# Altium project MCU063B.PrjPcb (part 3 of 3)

## Sheet MCU063B_Emulator.SchDoc
size 431 x 279 mm; Date: Not shown in title block; ApprovedBy: Not shown in title block; CheckedBy: Not shown in title block; Author: Not shown in title block; CompanyName: Not shown in title block; DrawnBy: Cody Watkins; Engineer: Not shown in title block; Organization: Not shown in title block; Address1: Not shown in title block; Address2: Not shown in title block; Address3: Not shown in title block; Address4: Not shown in title block; DocumentNumber: 9; Revision: Use project parameter SCH_Rev; SheetNumber: 9; SheetTotal: 11; PageSetup: Record=PageOptions¦CenterHorizontal=True¦CenterVertical=True¦PrintScale=1.00¦XCorrection=1.00¦YCorrection=1.00¦PrintKind=0¦BorderSize=5000000¦LeftOffset=0¦BottomOffset=0¦Orientation=2¦PaperLength=1000¦PaperWidth=1000¦Scale=100¦PaperSource=15¦PrintQuality=600¦MediaType=1¦DitherType=10¦PaperKind=Letter¦PrintScaleMode=1
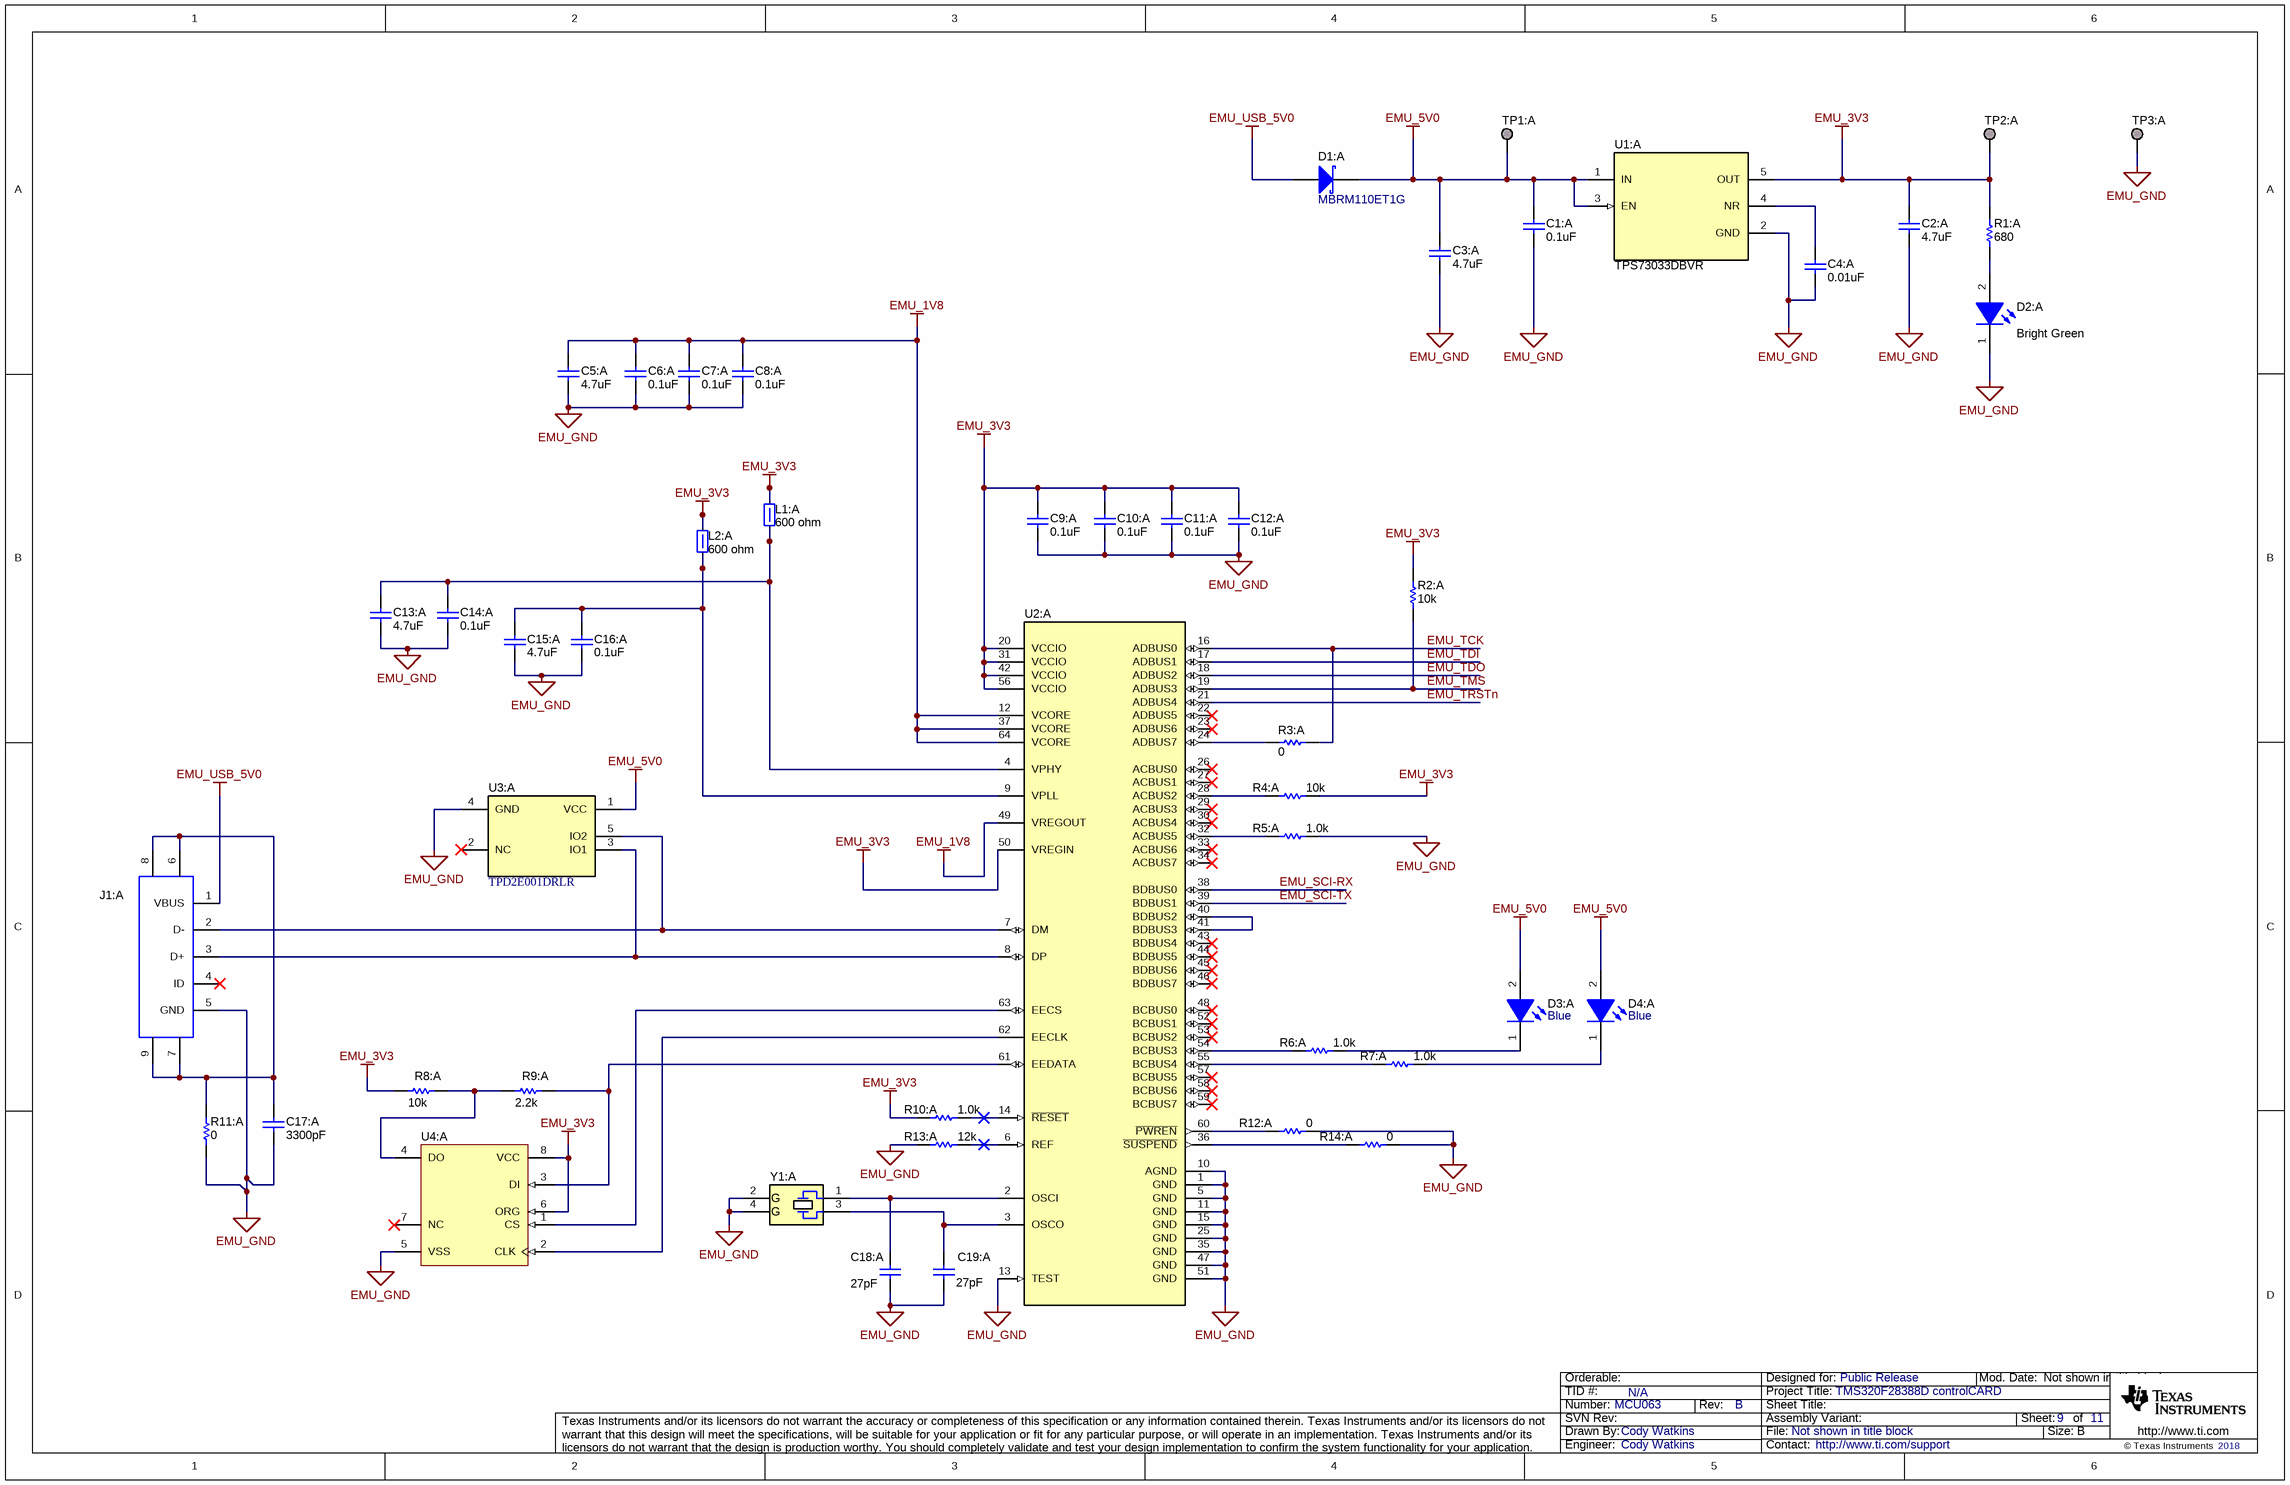
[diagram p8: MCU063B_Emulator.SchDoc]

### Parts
C1:A  ValueDisplayed: 0.1uF  [0402]  (hidden comment: CL05B104KP5NNNC)
C2:A  ValueDisplayed: 4.7uF  [0603]  (hidden comment: C0603C475K9PACTU)
C3:A  ValueDisplayed: 4.7uF  [0603]  (hidden comment: C0603C475K9PACTU)
C4:A  ValueDisplayed: 0.01uF  [0402]  (hidden comment: 0402ZC103KAT2A)
C5:A  ValueDisplayed: 4.7uF  [0603]  (hidden comment: C0603C475K9PACTU)
C6:A  ValueDisplayed: 0.1uF  [0402]  (hidden comment: CL05B104KP5NNNC)
C7:A  ValueDisplayed: 0.1uF  [0402]  (hidden comment: CL05B104KP5NNNC)
C8:A  ValueDisplayed: 0.1uF  [0402]  (hidden comment: CL05B104KP5NNNC)
C9:A  ValueDisplayed: 0.1uF  [0402]  (hidden comment: CL05B104KP5NNNC)
C10:A  ValueDisplayed: 0.1uF  [0402]  (hidden comment: CL05B104KP5NNNC)
C11:A  ValueDisplayed: 0.1uF  [0402]  (hidden comment: CL05B104KP5NNNC)
C12:A  ValueDisplayed: 0.1uF  [0402]  (hidden comment: CL05B104KP5NNNC)
C13:A  ValueDisplayed: 4.7uF  [0603]  (hidden comment: C0603C475K9PACTU)
C14:A  ValueDisplayed: 0.1uF  [0402]  (hidden comment: CL05B104KP5NNNC)
C15:A  ValueDisplayed: 4.7uF  [0603]  (hidden comment: C0603C475K9PACTU)
C16:A  ValueDisplayed: 0.1uF  [0402]  (hidden comment: CL05B104KP5NNNC)
C17:A  ValueDisplayed: 3300pF  [0402]  (hidden comment: CGA2B2X7R1H332K050BA)
C18:A  ValueDisplayed: 27pF  [0402]  (hidden comment: C0402C270J5GACTU)
C19:A  ValueDisplayed: 27pF  [0402]  (hidden comment: C0402C270J5GACTU)
D1:A  MBRM110ET1G  [POWERMITE]
D2:A  value Bright Green  [WL-SMCW_Green_0805]  (hidden comment: 150080VS75000)
D3:A  value Blue  [WL-SMCW_Blue_0805]  (hidden comment: 150080BS75000)
D4:A  value Blue  [WL-SMCW_Blue_0805]  (hidden comment: 150080BS75000)
J1:A  65100516121  [Wurth_65100516121]  (value not drawn)
L1:A  value 600 ohm  [0805_HV]  (hidden comment: HZ0805E601R-10)
L2:A  value 600 ohm  [0805_HV]  (hidden comment: HZ0805E601R-10)
R1:A  ValueDisplayed: 680  [0402]  (hidden comment: CRCW0402680RJNED)
R2:A  ValueDisplayed: 10k  [0402]  (hidden comment: CRCW040210K0JNED)
R3:A  ValueDisplayed: 0  [0402]  (hidden comment: CRCW04020000Z0ED)
R4:A  ValueDisplayed: 10k  [0402]  (hidden comment: CRCW040210K0JNED)
R5:A  ValueDisplayed: 1.0k  [0402]  (hidden comment: CRCW04021K00JNED)
R6:A  ValueDisplayed: 1.0k  [0402]  (hidden comment: CRCW04021K00JNED)
R7:A  ValueDisplayed: 1.0k  [0402]  (hidden comment: CRCW04021K00JNED)
R8:A  ValueDisplayed: 10k  [0402]  (hidden comment: CRCW040210K0JNED)
R9:A  ValueDisplayed: 2.2k  [0402]  (hidden comment: CRCW04022K20JNED)
R10:A  ValueDisplayed: 1.0k  [0402]  (hidden comment: CRCW04021K00JNED)
R11:A  ValueDisplayed: 0  [0402]  (hidden comment: CRCW04020000Z0ED)
R12:A  ValueDisplayed: 0  [0402]  (hidden comment: CRCW04020000Z0ED)
R13:A  ValueDisplayed: 12k  [0402]  (hidden comment: CRCW040212K0JNED)
R14:A  ValueDisplayed: 0  [0402]  (hidden comment: CRCW04020000Z0ED)
TP1:A  TESTPOINT  [TP_50MIL-25MILHOLE]  (value not drawn)  (no BOM)
TP2:A  TESTPOINT  [TP_50MIL-25MILHOLE]  (value not drawn)  (no BOM)
TP3:A  TESTPOINT  [TP_50MIL-25MILHOLE]  (value not drawn)  (no BOM)
U1:A  TPS73033DBVR  [DBV0005A_N]
U2:A  FT2232HL-REEL  [LQFP64_N]  (value not drawn)
U3:A  TPD2E001DRLR  [DRL0005A]
U4:A  93LC56C-I/SN  [SOIC-8]  (value not drawn)
Y1:A  ECS-120-20-30B-TR  [ECS_ECX-53B]  (value not drawn)

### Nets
EMU_1V8: C5:A.2 C6:A.2 C7:A.2 C8:A.2 U2:A.12(VCORE) U2:A.37(VCORE) U2:A.49(VREGOUT) U2:A.64(VCORE)
EMU_3V3: C2:A.1 C9:A.2 C10:A.2 C11:A.2 C12:A.2 L1:A.2 L2:A.2 R1:A.1 R2:A.2 R4:A.2 R8:A.1 R10:A.1 TP2:A.1 U1:A.5(OUT) U2:A.20(VCCIO) U2:A.31(VCCIO) U2:A.42(VCCIO) U2:A.50(VREGIN) U2:A.56(VCCIO) U4:A.6(ORG) U4:A.8(VCC)
EMU_5V0: C1:A.2 C3:A.1 D1:A.1(K) D3:A.2(A) D4:A.2(A) TP1:A.1 U1:A.1(IN) U1:A.3(EN) U3:A.1(VCC)
EMU_GND: C1:A.1 C2:A.2 C3:A.2 C4:A.1 C5:A.1 C6:A.1 C7:A.1 C8:A.1 C9:A.1 C10:A.1 C11:A.1 C12:A.1 C13:A.2 C14:A.1 C15:A.2 C16:A.1 C17:A.1 C18:A.1 C19:A.1 D2:A.1(K) J1:A.5(GND) R5:A.2 R11:A.2 R12:A.1 R13:A.1 R14:A.1 TP3:A.1 U1:A.2(GND) U2:A.1(GND) U2:A.5(GND) U2:A.10(AGND) U2:A.11(GND) U2:A.13(TEST) U2:A.15(GND) U2:A.25(GND) U2:A.35(GND) U2:A.47(GND) U2:A.51(GND) U3:A.4(GND) U4:A.5(VSS) Y1:A.2(GND) Y1:A.4(GND)
EMU_USB_5V0: D1:A.2(A) J1:A.1(VBUS)
EMU_SCI-RX: U2:A.38(BDBUS0)
EMU_SCI-TX: U2:A.39(BDBUS1)
EMU_TCK: R3:A.1 U2:A.16(ADBUS0)
EMU_TDI: U2:A.17(ADBUS1)
EMU_TDO: U2:A.18(ADBUS2)
EMU_TMS: R2:A.1 U2:A.19(ADBUS3)
EMU_TRSTn: U2:A.21(ADBUS4)
NetC4:A_2: C4:A.2 U1:A.4(NR)
NetC13:A_1: C13:A.1 C14:A.2 L1:A.1 U2:A.4(VPHY)
NetC15:A_1: C15:A.1 C16:A.2 L2:A.1 U2:A.9(VPLL)
NetC17:A_2: C17:A.2 J1:A.6 J1:A.7 J1:A.8 J1:A.9 R11:A.1
NetC18:A_2: C18:A.2 U2:A.2(OSCI) Y1:A.1
NetC19:A_2: C19:A.2 U2:A.3(OSCO) Y1:A.3
NetD2:A_2: D2:A.2(A) R1:A.2
NetD3:A_1: D3:A.1(K) R6:A.2
NetD4:A_1: D4:A.1(K) R7:A.2
NetJ1:A_2: J1:A.2(D-) U2:A.7(DM) U3:A.5(IO2)
NetJ1:A_3: J1:A.3(D+) U2:A.8(DP) U3:A.3(IO1)
NetR3:A_2: R3:A.2 U2:A.24(ADBUS7)
NetR4:A_1: R4:A.1 U2:A.28(ACBUS2)
NetR5:A_1: R5:A.1 U2:A.32(ACBUS5)
NetR6:A_1: R6:A.1 U2:A.54(BCBUS3)
NetR7:A_1: R7:A.1 U2:A.55(BCBUS4)
NetR8:A_2: R8:A.2 R9:A.1 U4:A.4(DO)
NetR9:A_2: R9:A.2 U2:A.61(EEDATA) U4:A.3(DI)
NetR10:A_2: R10:A.2 U2:A.14(~{RESET})
NetR12:A_2: R12:A.2 U2:A.60(~{PWREN})
NetR13:A_2: R13:A.2 U2:A.6(REF)
NetR14:A_2: R14:A.2 U2:A.36(~{SUSPEND})
NetU2:A_40: U2:A.40(BDBUS2) U2:A.41(BDBUS3)
NetU2:A_62: U2:A.62(EECLK) U4:A.2(CLK)
NetU2:A_63: U2:A.63(EECS) U4:A.1(CS)

Not connected (* = marked no-connect by the designer): J1:A 4(ID)*; U2:A 22(ADBUS5)* 23(ADBUS6)* 26(ACBUS0)* 27(ACBUS1)* 29(ACBUS3)* 30(ACBUS4)* 33(ACBUS6)* 34(ACBUS7)* 43(BDBUS4)* 44(BDBUS5)* 45(BDBUS6)* 46(BDBUS7)* 48(BCBUS0)* 52(BCBUS1)* 53(BCBUS2)* 57(BCBUS5)* 58(BCBUS6)* 59(BCBUS7)*; U3:A 2(NC)*; U4:A 7(NC)*

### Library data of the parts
C1:A C6:A C7:A C8:A C9:A C10:A C11:A C12:A C14:A C16:A = CMP-0006343-2: CAP, CERM, 0.1 uF, 10 V, +/- 10%, X7R, 0402; Manufacturer: Samsung Electro-Mechanics; Polarized: N; Value: 0.1uF; U/M: EA; Cap_F: 100nF; Value1: Unknown; VDC_V: 10V; TaMin_C: -55°C; TaMax_C: 125°C; AEC Category: Q200; SizeArea_mm2: 0.5; SizeAreaWB_mm2: 3; SizeX_mm: 1; SizeZ_mm: 0.6
C2:A C3:A C5:A C13:A C15:A = CMP-0006950-5: CAP, CERM, 4.7 uF, 6.3 V, +/- 10%, X5R, 0603; Manufacturer: Kemet; TaMin_C: -55°C; ESR_ohm: 6m; Polarized: N; SizeAreaWB_mm2: 4.68; Value1: 0.006 ohm; U/M: EA; Value: 4.7uF; TaMax_C: 85°C; SizeZ_mm: 1; SizeX_mm: 1.6; SizeY_mm: 0.8; Value2: 6.3V; SizeArea_mm2: 1.28; Cap_F: 4.7µF; IRMS_A: 7.24A; AEC Category: Q200
C4:A = CMP-0006203-2: CAP, CERM, 0.01 uF, 10 V, +/- 10%, X7R, 0402; Manufacturer: AVX; Polarized: N; Value: 0.01uF; U/M: EA; Cap_F: 10nF; Value1: Unknown; Value2: 10V; TaMin_C: -55°C; TaMax_C: 125°C; AEC Category: Q200; SizeArea_mm2: 0.5; SizeAreaWB_mm2: 3; SizeX_mm: 1; SizeZ_mm: 0.6
C17:A = CMP-0006319-2: CAP, CERM, 3300 pF, 50 V, +/- 10%, X7R, AEC-Q200 Grade 1, 0402; Manufacturer: TDK; TaMin_C: -55°C; ESR_ohm: 7.85178d; Polarized: N; SizeAreaWB_mm2: 3; Value1: 0.785178 ohm; U/M: EA; Value: 3300pF; TaMax_C: 125°C; SizeZ_mm: 0.6; SizeX_mm: 1; SizeY_mm: 0.5; Value2: 50V; AEC Qualified: Y; Cap_F: 3.3nF; IRMS_A: 2.72902dA; AEC Category: Q200
C18:A C19:A = CMP-0750098-1: CAP, CERM, 27 pF, 50 V,+/- 5%, C0G/NP0, 0402; Manufacturer: Kemet; SizeX_mm: 1; TaMin_C: -55°C; Value: 27pF; Polarized: N; SizeAreaWB_mm2: 3; SizeArea_mm2: 0.5; Green_REACh: Passed; Green_Lifecycle: Active; Value2: 50V; U/M: EA; AEC Category: Q200; SizeZ_mm: 0.6; TaMax_C: 125°C
D1:A = CMP-0028747-2: Diode, Schottky, 10 V, 1 A, AEC-Q101, POWERMITE; Manufacturer: ON Semiconductor; Vf_V: 530mV; Value: 10V; Value1: 1A; Value2: 0.53V; TJmax_C: 150°C; AEC Category: Q101; AEC Qualified: Y; SizeAreaWB_mm2: 14.945; SizeArea_mm2: 7.995; SizeX_mm: 3.9; SizeY_mm: 2.05; SizeZ_mm: 1.15; Green_Lifecycle: Not Set; Green_REACh: Incomplete
D2:A = CMP-0002960-2: LED, Bright Green, SMD; Manufacturer: Wurth Elektronik; Type: AlInGaP; Vf_V: 2V; Io_A: 20mA; Vr_V: 5V; Tjmax_C: 85°C; Power_TotalModule: 72mW; Value1: 0.072W; Angle: 140; U/M: EA
D3:A D4:A = CMP-0002959-3: LED, Blue, SMD; Manufacturer: Wurth Elektronik; Vf_V: 3.2V; Value1: 0.105W; Angle: 140; Type: InGaN; Power_TotalModule: 105mW; Tjmax_C: 85°C; Vr_V: 5V; Io_A: 20mA
J1:A = CMP-0054809-1: Connector, Receptacle, USB Mini B 2.0, SMT; Manufacturer: Wurth Elektronik; Pitch_mm: 0.8; Gender: Female; Row_Count: 1; ContactFinish: Gold; Current_A: 1A; Voltage_V: 30V; Cert_UL: Y; CNHeader: FALSE; CT: TRUE; Green_Lifecycle: Active; Green_REACh: Passed
L1:A L2:A = CMP-0003398-1: Ferrite Bead, 600 ohm @ 100 MHz, 0.5 A, 0805; Manufacturer: Laird-Signal Integrity Products; Imax_A: 5dA; DCR_ohm: 3d; Value1: 0.3 ohm; Value2: 0.5A; ZTyp@100MHz_Ohm: 600; SizeArea_mm2: 2.5; SizeAreaWB_mm2: 6.75; SizeX_mm: 2; SizeY_mm: 1.25; SizeZ_mm: 1.45
R1:A = CMP-0026962-3: RES, 680, 5%, 0.063 W, AEC-Q200 Grade 0, 0402; Manufacturer: Vishay-Dale; Value: 680; Value_Code: 680R; Power_W: 63mW; Value2: 0.063W; VDC_V: 50V; TempCo: 200 ppm/C; EIA_Code: E24; AEC Category: Q200; AEC Qualified: Y; AEC Grade: 0; SizeArea_mm2: 0.5; SizeX_mm: 1; SizeZ_mm: 0.6
R2:A R4:A R8:A = CMP-0026825-5: RES, 10 k, 5%, 0.063 W, AEC-Q200 Grade 0, 0402; Manufacturer: Vishay-Dale; Value: 10k; Value_Code: 10k0; Power_W: 63mW; Value2: 0.063W; VDC_V: 50V; TempCo: 200 ppm/C; EIA_Code: E24; AEC Category: Q200; AEC Qualified: Y; AEC Grade: 0; SizeArea_mm2: 0.5; SizeX_mm: 1; SizeZ_mm: 0.6
R3:A R11:A R12:A R14:A = CMP-0026822-3: RES, 0, 5%, 0.063 W, AEC-Q200 Grade 0, 0402; Manufacturer: Vishay-Dale; Value: 0; Value_Code: 0000; Power_W: 63mW; Value2: 0.063W; VDC_V: 50V; TempCo: 200 ppm/C; EIA_Code: E24; AEC Category: Q200; AEC Qualified: Y; SizeArea_mm2: 0.5; SizeX_mm: 1; SizeZ_mm: 0.6
R5:A R6:A R7:A R10:A = CMP-0026852-3: RES, 1.0 k, 5%, 0.063 W, AEC-Q200 Grade 0, 0402; Manufacturer: Vishay-Dale; Value: 1.0k; Res_ohm: 1k; Value_Code: 1k00; Power_W: 63mW; Value2: 0.063W; VDC_V: 50V; TempCo: 200 ppm/C; EIA_Code: E24; AEC Category: Q200; AEC Qualified: Y; AEC Grade: 0; SizeArea_mm2: 0.5; SizeX_mm: 1; SizeZ_mm: 0.6
R9:A = CMP-0026890-5: RES, 2.2 k, 5%, 0.063 W, AEC-Q200 Grade 0, 0402; Manufacturer: Vishay-Dale; Value: 2.2k; Value_Code: 2k20; Power_W: 63mW; Value2: 0.063W; VDC_V: 50V; TempCo: 200 ppm/C; EIA_Code: E24; AEC Category: Q200; AEC Qualified: Y; AEC Grade: 0; SizeArea_mm2: 0.5; SizeX_mm: 1; SizeZ_mm: 0.6
R13:A = CMP-0026834-3: RES, 12 k, 5%, 0.063 W, AEC-Q200 Grade 0, 0402; Manufacturer: Vishay-Dale; Value: 12k; Value_Code: 12k0; Power_W: 63mW; Value2: 0.063W; VDC_V: 50V; TempCo: 200 ppm/C; EIA_Code: E24; AEC Category: Q200; AEC Qualified: Y; AEC Grade: 0; SizeArea_mm2: 0.5; SizeX_mm: 1; SizeZ_mm: 0.6
TP1:A TP2:A TP3:A = CMP-0078143-3: TEST POINT.  No entry in BOM.
U1:A = CMP-0073823-1: Low-Noise, High PSRR, RF 200-mA Low-Dropout Linear Regulators, DBV0005A (SOT-23-5); Alternate PartNumber: TPS73033DBVT; Manufacturer: Texas Instruments; CompType: IC; U/M: EA; SizeArea_mm2: 8.12; SizeAreaWB_mm2: 14.82; SizeX_mm: 2.8; SizeY_mm: 2.9; SizeZ_mm: 1.45; Green_Lifecycle: Active; Green_REACh: Passed
U2:A = CMP-0004796-1: Dual High Speed USB To Multipurpose UART/FIFO IC, LQFP-64; Manufacturer: FTDI
U3:A = CMP-0043096-2: Low-Capacitance + / - 15 kV ESD-Protection Array for High-Speed Data Interfaces, 2 Channels, -40 to +85 degC, 5-pin SOT (DRL), Green (RoHS & no Sb/Br); Manufacturer: Texas Instruments; Breakdown Voltage(Min)(V): 11; IEC 61000-4-2 Air-Gap(+/- kV): 15; IEC 61000-4-2 Contact(+/- kV): 8; IO Capacitance(Typ)(pF): 1.5; IO Leakage Current(nA): 1; SubFamily: ESD Solution; USB High Speed: TRUE
U4:A = CMP-0005261-2: 2K Microwire Compatible Serial EEPROM, SOIC-8; Manufacturer: Microchip; SizeAreaWB_mm2: 55.131; SizeArea_mm2: 29.351; SizeX_mm: 5.99; SizeY_mm: 4.9; SizeZ_mm: 1.75
Y1:A = CMP-0004646-3: Crystal, 12 MHz, 20pF, SMD; Manufacturer: ECS Inc.; TaMin_C: -20°C; TaMax_C: 70°C; Frequency Stability: +/-50ppm; Frequency_Fixed: 12MHz

## Sheet MCU063B_Emulator_interface.SchDoc
size 431 x 279 mm; Date: Not shown in title block; ApprovedBy: Not shown in title block; CheckedBy: Not shown in title block; Author: Not shown in title block; CompanyName: Not shown in title block; DrawnBy: Cody Watkins; Engineer: Not shown in title block; Organization: Not shown in title block; Address1: Not shown in title block; Address2: Not shown in title block; Address3: Not shown in title block; Address4: Not shown in title block; DocumentNumber: 10; Revision: Use project parameter SCH_Rev; SheetNumber: 10; SheetTotal: 11; PageSetup: Record=PageOptions¦CenterHorizontal=True¦CenterVertical=True¦PrintScale=1.00¦XCorrection=1.00¦YCorrection=1.00¦PrintKind=0¦BorderSize=5000000¦LeftOffset=0¦BottomOffset=0¦Orientation=2¦PaperLength=1000¦PaperWidth=1000¦Scale=100¦PaperSource=15¦PrintQuality=600¦MediaType=1¦DitherType=10¦PaperKind=Letter¦PrintScaleMode=1
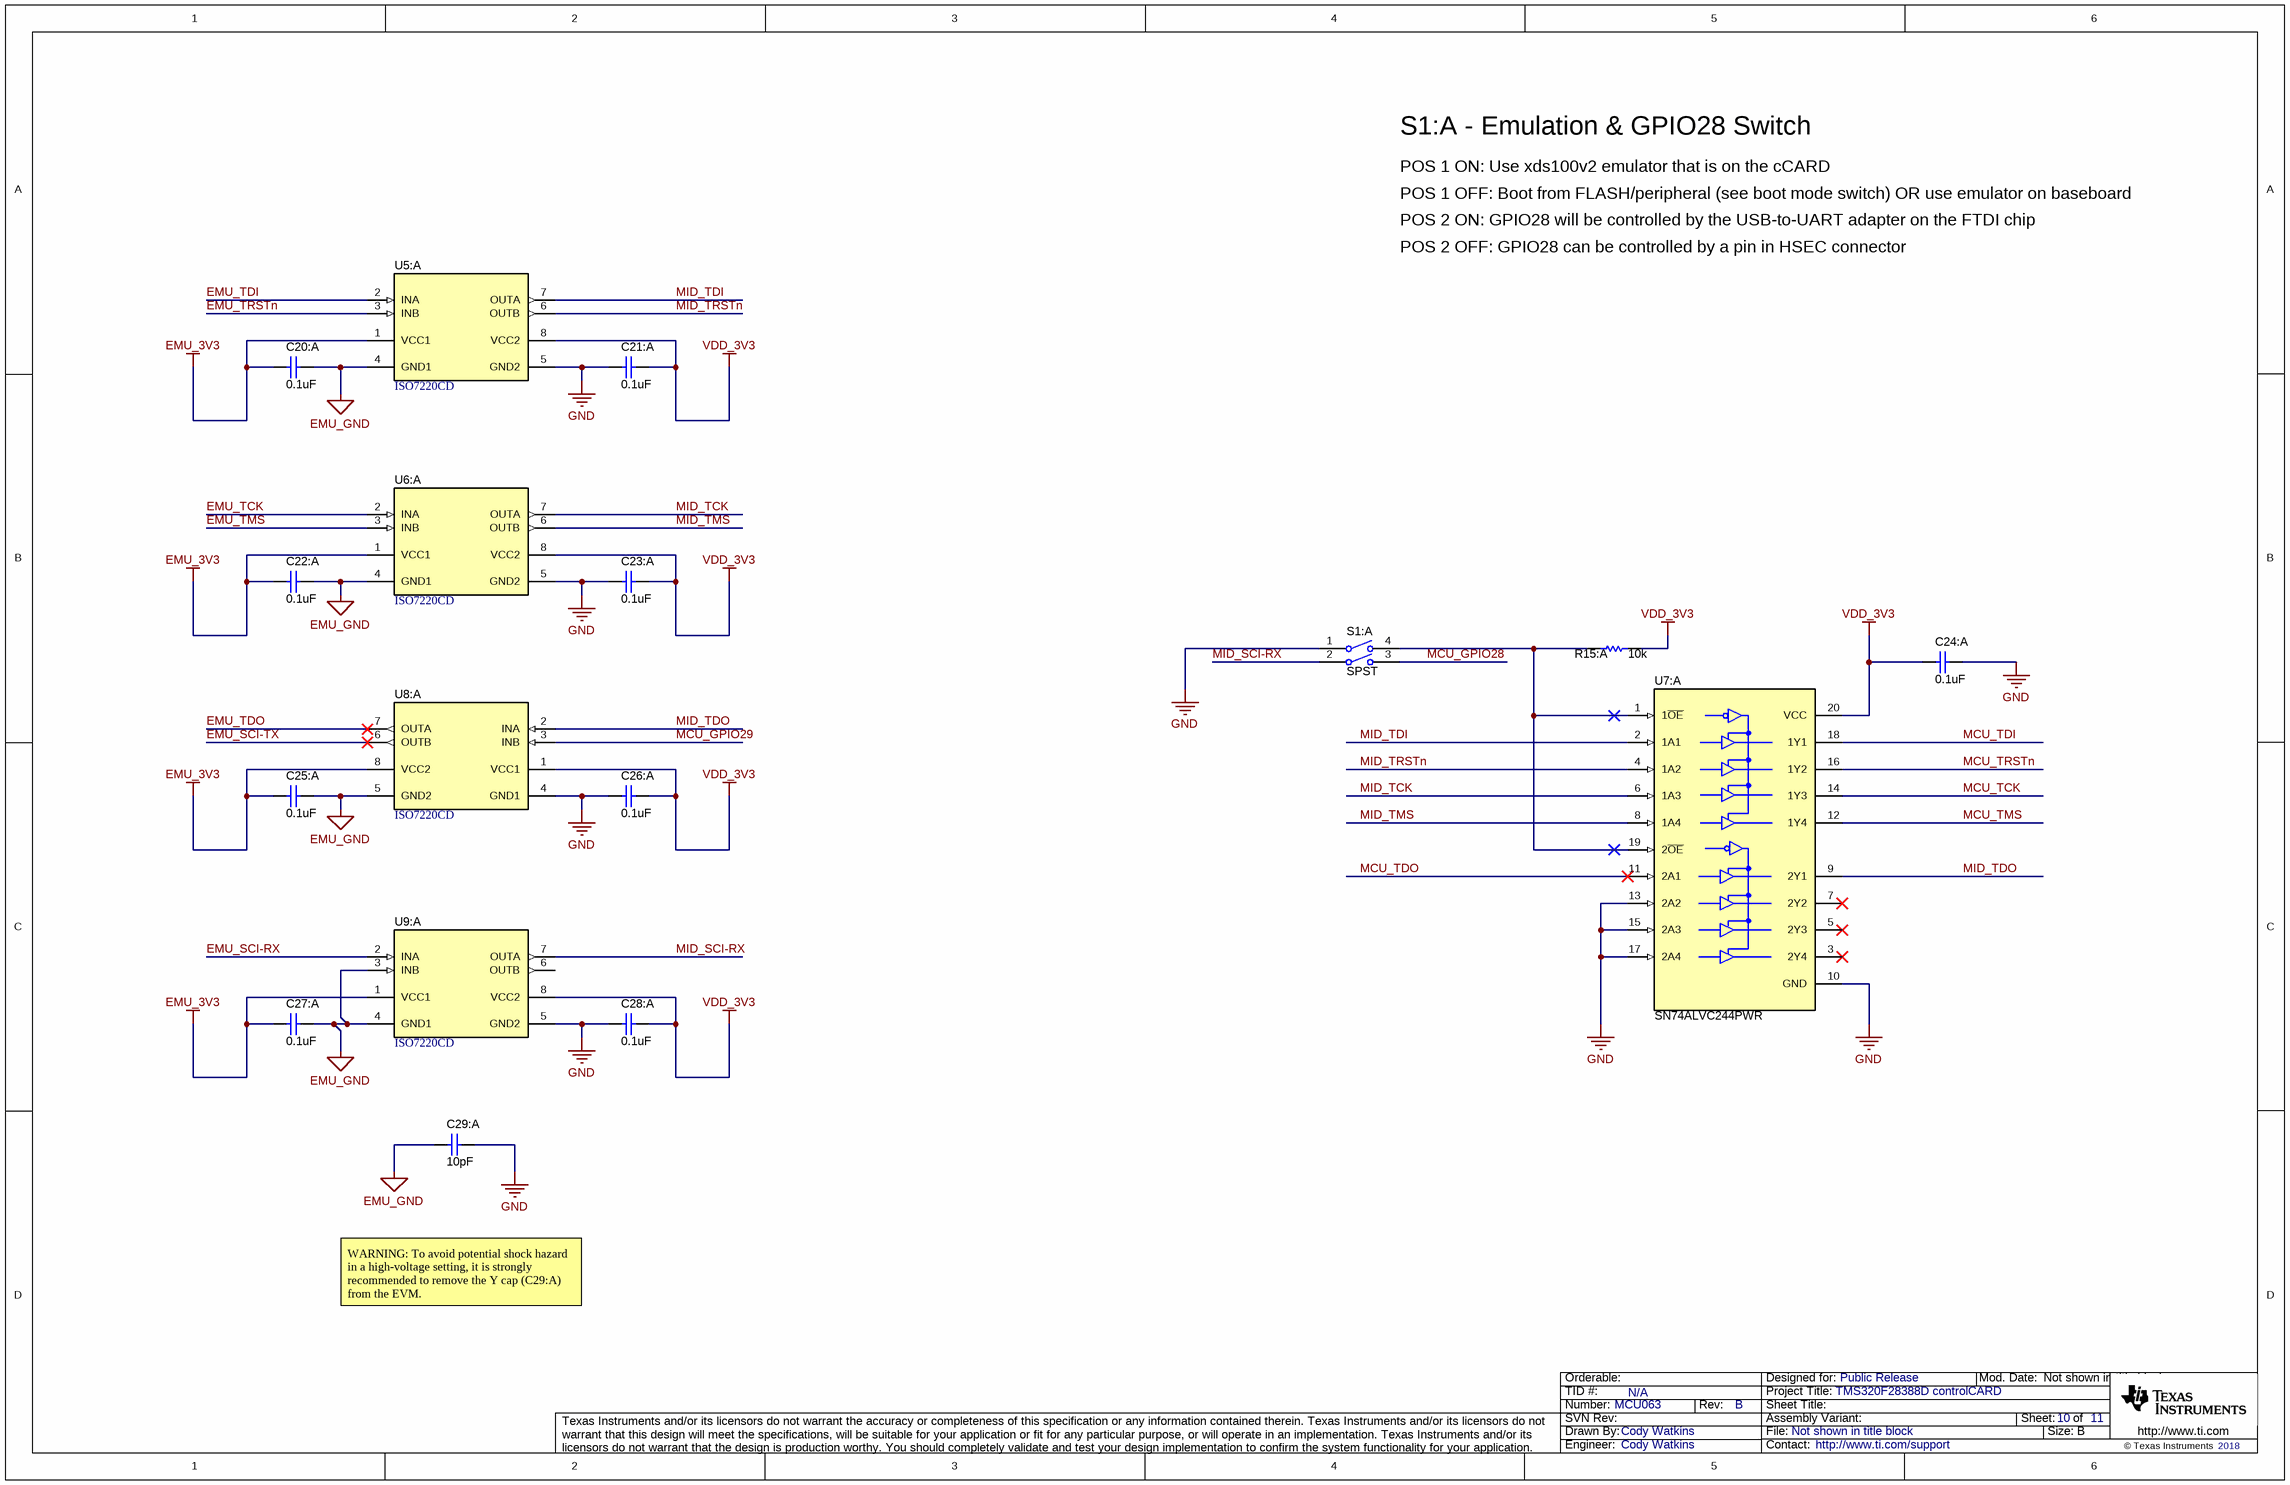
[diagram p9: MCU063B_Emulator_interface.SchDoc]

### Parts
C20:A  ValueDisplayed: 0.1uF  [0402]  (hidden comment: CL05B104KP5NNNC)
C21:A  ValueDisplayed: 0.1uF  [0402]  (hidden comment: CL05B104KP5NNNC)
C22:A  ValueDisplayed: 0.1uF  [0402]  (hidden comment: CL05B104KP5NNNC)
C23:A  ValueDisplayed: 0.1uF  [0402]  (hidden comment: CL05B104KP5NNNC)
C24:A  ValueDisplayed: 0.1uF  [0402]  (hidden comment: CL05B104KP5NNNC)
C25:A  ValueDisplayed: 0.1uF  [0402]  (hidden comment: CL05B104KP5NNNC)
C26:A  ValueDisplayed: 0.1uF  [0402]  (hidden comment: CL05B104KP5NNNC)
C27:A  ValueDisplayed: 0.1uF  [0402]  (hidden comment: CL05B104KP5NNNC)
C28:A  ValueDisplayed: 0.1uF  [0402]  (hidden comment: CL05B104KP5NNNC)
C29:A  ValueDisplayed: 10pF  [1812_180]  (hidden comment: C1812C100JHGACTU)
R15:A  ValueDisplayed: 10k  [0402]  (hidden comment: CRCW040210K0JNED)
S1:A  Circuit: SPST  [SW_218-2LP]  (hidden comment: 218-2LPST)
U5:A  ISO7220CD  [D0008B_N]
U6:A  ISO7220CD  [D0008B_N]
U7:A  SN74ALVC244PWR  [PW0020A_N]
U8:A  ISO7220CD  [D0008B_N]
U9:A  ISO7220CD  [D0008B_N]

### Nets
EMU_3V3: C20:A.2 C22:A.2 C25:A.2 C27:A.2 U5:A.1(VCC1) U6:A.1(VCC1) U8:A.8(VCC2) U9:A.1(VCC1)
EMU_GND: C20:A.1 C22:A.1 C25:A.1 C27:A.1 C29:A.2 U5:A.4(GND1) U6:A.4(GND1) U8:A.5(GND2) U9:A.3(INB) U9:A.4(GND1)
GND: C21:A.2 C23:A.2 C24:A.1 C26:A.2 C28:A.2 C29:A.1 S1:A.1 U5:A.5(GND2) U6:A.5(GND2) U7:A.10(GND) U7:A.13(2A2) U7:A.15(2A3) U7:A.17(2A4) U8:A.4(GND1) U9:A.5(GND2)
VDD_3V3: C21:A.1 C23:A.1 C24:A.2 C26:A.1 C28:A.1 R15:A.2 U5:A.8(VCC2) U6:A.8(VCC2) U7:A.20(VCC) U8:A.1(VCC1) U9:A.8(VCC2)
EMU_SCI-RX: U9:A.2(INA)
EMU_SCI-TX: U8:A.6(OUTB)
EMU_TCK: U6:A.2(INA)
EMU_TDI: U5:A.2(INA)
EMU_TDO: U8:A.7(OUTA)
EMU_TMS: U6:A.3(INB)
EMU_TRSTn: U5:A.3(INB)
MCU_GPIO28: S1:A.3
MCU_GPIO29: U8:A.3(INB)
MCU_TCK: U7:A.14(1Y3)
MCU_TDI: U7:A.18(1Y1)
MCU_TDO: U7:A.11(2A1)
MCU_TMS: U7:A.12(1Y4)
MCU_TRSTn: U7:A.16(1Y2)
MID_SCI-RX: S1:A.2 U9:A.7(OUTA)
MID_TCK: U6:A.7(OUTA) U7:A.6(1A3)
MID_TDI: U5:A.7(OUTA) U7:A.2(1A1)
MID_TDO: U7:A.9(2Y1) U8:A.2(INA)
MID_TMS: U6:A.6(OUTB) U7:A.8(1A4)
MID_TRSTn: U5:A.6(OUTB) U7:A.4(1A2)
NetR15:A_1: R15:A.1 S1:A.4 U7:A.1(1~{OE}) U7:A.19(2~{OE})

Not connected (* = marked no-connect by the designer): U7:A 3(2Y4)* 5(2Y3)* 7(2Y2)*; U9:A 6(OUTB)

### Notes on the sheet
- S1:A - Emulation & GPIO28 Switch
- POS 1 ON: Use xds100v2 emulator that is on the cCARD
- POS 1 OFF: Boot from FLASH/peripheral (see boot mode switch) OR use emulator on baseboard
- POS 2 ON: GPIO28 will be controlled by the USB-to-UART adapter on the FTDI chip
- POS 2 OFF: GPIO28 can be controlled by a pin in HSEC connector
- WARNING: To avoid potential shock hazard in a high-voltage setting, it is strongly recommended to remove the Y cap (C29:A) from the EVM.

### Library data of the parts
C20:A C21:A C22:A C23:A C24:A C25:A C26:A C27:A C28:A = CMP-0006343-2: as C1:A on sheet MCU063B_Emulator
C29:A = CMP-0082066-1: CAP, CERM, 10 pF, 3000 V,+/- 5%, C0G/NP0, AEC-Q200 Grade 1, 1812; Manufacturer: Kemet; SizeAreaWB_mm2: 23.1; SizeArea_mm2: 14.4; AEC Qualified: Y; AEC Category: Q200; Value: 10pF; TaMax_C: 125°C; SizeZ_mm: 1.8; AEC Grade: 1; Polarized: N; TaMin_C: -55°C; SizeY_mm: 3.2; Value2: 3000V; U/M: EA; SizeX_mm: 4.5; Cap_Case: 1812
R15:A = CMP-0026825-5: as R2:A on sheet MCU063B_Emulator
S1:A = CMP-0002230-1: Switch, SPST, 2 Pos, 25mA, 24VDC, SMD; Manufacturer: CTS Electrocomponents; VDC_V: 24V; SwitchFunction: Off-On; PositionCount: 2; CurrentRating_mA: 25A
U5:A U6:A U8:A U9:A = CMP-0029375-1: 25 Mbps Dual Channels, 2 / 0, Digital Isolator, 3.3 V / 5 V, -40 to +125 degC, 8-pin SOIC (D), Green (RoHS & no Sb/Br); Manufacturer: Texas Instruments; Datarate(Mbps): 25; Input Noise Filter: Yes; Insulation Rating(VRMS): 2500; Prop Delay(Max)(ns): 42; Rating: Catalog; Supply Voltage(s)(V): 3.3, 5; TTL/CMOS Input Threshold: TTL
U7:A = CMP-0047070-3: Octal Buffer/Driver With 3-State OUtputs, PW0020A (TSSOP-20); Manufacturer: Texas Instruments; Bits(#): 8; F @ Nom Voltage(Max)(Mhz): 100; ICC @ Nom Voltage(Max)(mA): 0.024; Input Type: LVTTL; Rating: Catalog; tpd @ Nom Voltage(Max)(ns): 4.4,3.1,2.8; VCC(Max)(V): 3.6; VCC(Min)(V): 1.65; Voltage(Nom)(V): 1.8,2.5,2.7,3.3; AEC Category: Q200; AEC Qualified: N; CompType: IC; SizeArea_mm2: 43.56; SizeAreaWB_mm2: 73.96; SizeX_mm: 6.6; SizeZ_mm: 1.2

## Sheet MCU063B_EVM_Hardware.SchDoc
size 431 x 279 mm; Date: Not shown in title block; ApprovedBy: Not shown in title block; CheckedBy: Not shown in title block; Author: Not shown in title block; CompanyName: Not shown in title block; Engineer: Not shown in title block; Organization: Not shown in title block; Address1: Not shown in title block; Address2: Not shown in title block; Address3: Not shown in title block; Address4: Not shown in title block; DocumentNumber: 11; Revision: Use project parameter SCH_Rev; SheetNumber: 11; SheetTotal: 11; PageSetup: Record=PageOptions¦CenterHorizontal=True¦CenterVertical=True¦PrintScale=1.00¦XCorrection=1.00¦YCorrection=1.00¦PrintKind=0¦BorderSize=5000000¦LeftOffset=0¦BottomOffset=0¦Orientation=2¦PaperLength=1000¦PaperWidth=1000¦Scale=100¦PaperSource=15¦PrintQuality=600¦MediaType=1¦DitherType=10¦PaperKind=Letter¦PrintScaleMode=1
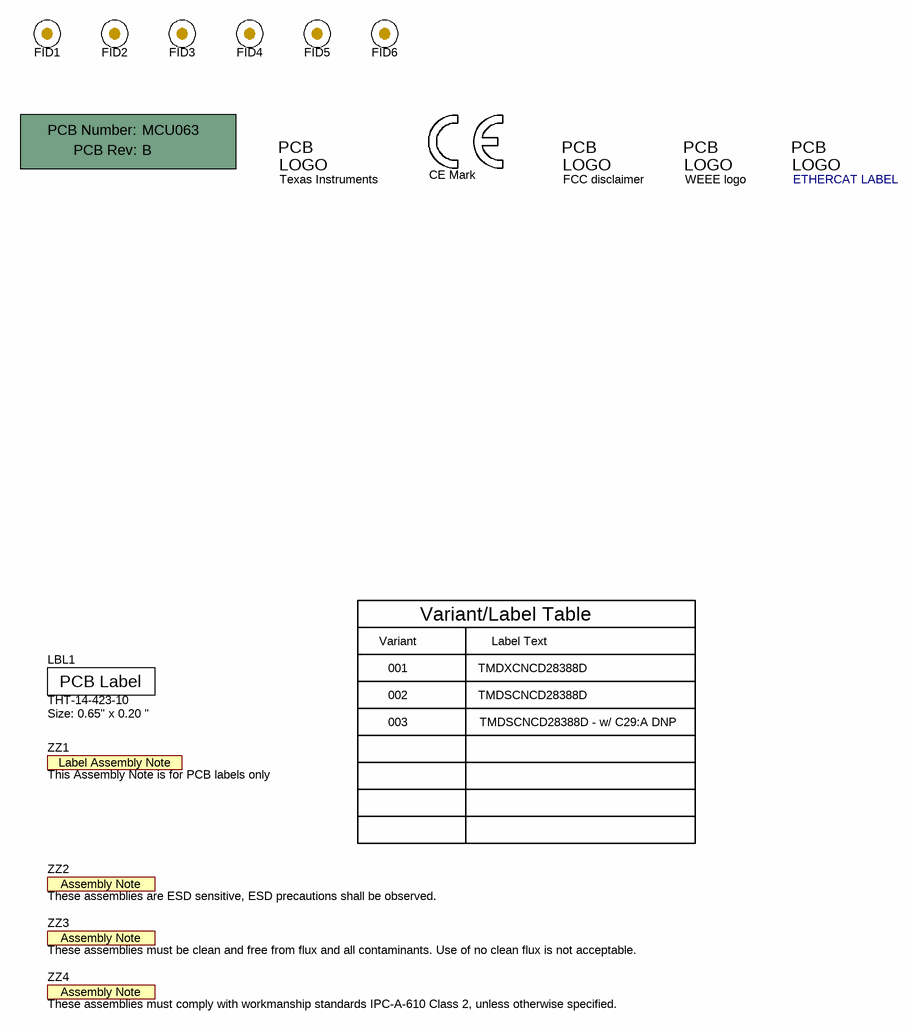
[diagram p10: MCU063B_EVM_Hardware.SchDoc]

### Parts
!PCB1  Printed Circuit Board  (value not drawn)  (mechanical)
FID1  Fiducial  [Fiducial10-20]  (value not drawn)
FID2  Fiducial  [Fiducial10-20]  (value not drawn)
FID3  Fiducial  [Fiducial10-20]  (value not drawn)
FID4  Fiducial  [Fiducial10-20]  (value not drawn)
FID5  Fiducial  [Fiducial10-20]  (value not drawn)
FID6  Fiducial  [Fiducial10-20]  (value not drawn)
LBL1  THT-14-423-10  Note: Size: 0.65" x 0.20 "  [Label_650x200]
Logo1  CE Mark  [CE_Mark_5mm]  (no BOM)
Logo2  Texas Instruments  [TI_Stacked_Overlay_Small]  (no BOM)
Logo3  FCC disclaimer  [FCC_disclaimer]  (no BOM)
Logo4  WEEE logo  [WEEE_Minimum]  (no BOM)
Logo5  ETHERCAT LABEL  [EtherCAT_label]  (no BOM)
ZZ1  This Assembly Note is for PCB labels only  [AssemblyNoteLabel]  (no BOM)
ZZ2  These assemblies are ESD sensitive, ESD precautions shall be observed.  [AssemblyNote]  (no BOM)
ZZ3  These assemblies must be clean and free from flux and all contaminants. Use of no clean flux is not acceptable.  [AssemblyNote]  (no BOM)
ZZ4  These assemblies must comply with workmanship standards IPC-A-610 Class 2, unless otherwise specified.  [AssemblyNote]  (no BOM)

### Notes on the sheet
- Variant
- Variant/Label Table
- Label Text
- 001
- 002
- TMDXCNCD28388D
- TMDSCNCD28388D
- 003
- TMDSCNCD28388D - w/ C29:A DNP

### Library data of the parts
!PCB1 = CMP-0003618-2: Manufacturer: Any; PartNumber: MCU063
FID1-FID6 = CMP-0077181-1: Fiducial mark.  There is nothing to buy or mount.
LBL1 = CMP-0003625-1: Thermal Transfer Printable Labels, 0.650" W x 0.200" H - 10,000 per roll; Manufacturer: Brady
Logo1 = CMP-0074844-1: SymbolCreator: a0412235
Logo2 = CMP-0074838-1: Texas Instrument Corporate Signature; SymbolCreator: a0412235; Lib Reference: TI_Logo; Library Reference: Logo
Logo3 = CMP-0074847-1: FCC_disclaimer
Logo4 = CMP-0074769-1
Logo5 = CMP-0084011-3: EtherCAT logo
ZZ1 = CMP-0003616-3
ZZ2 = CMP-0077236-1
ZZ3 = CMP-0077237-1
ZZ4 = CMP-0077238-1

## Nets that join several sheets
3V3: MCU063B_GPIO (EC1.119), MCU063B_Support (J2.10), MCU063B_Power (10 pins)
EMU_3V3: MCU063B_Emulator (21 pins), MCU063B_Emulator_interface (8 pins)
EMU_GND: MCU063B_Emulator (42 pins), MCU063B_Emulator_interface (10 pins)
GND: MCU063B_GPIO (15 pins), MCU063B_Support (31 pins), MCU063B_ADC (49 pins), MCU063B_Power (120 pins), MCU063B_USB (11 pins), MCU063B_EtherNET (19 pins), MCU063B_EtherCAT (59 pins), MCU063B_Emulator_interface (15 pins)
HSEC_5V0: MCU063B_GPIO (6 pins), MCU063B_Power (D3.2 TP7.1)
USB_5V0: MCU063B_Power (R82.2), MCU063B_USB (5 pins)
VDD_1V2: MCU063B_GPIO (EC1.118), MCU063B_Support (U4.3), MCU063B_Power (25 pins)
VDD_3V3: MCU063B_GPIO (R1.2 R2.1), MCU063B_Support (26 pins), MCU063B_Power (51 pins), MCU063B_USB (R104.1), MCU063B_EtherNET (30 pins), MCU063B_EtherCAT (73 pins), MCU063B_Emulator_interface (11 pins)
VDDA_3V3: MCU063B_ADC (18 pins), MCU063B_Power (6 pins)
ADC_A0A1_N: MCU063B_GPIO (EC1.11), MCU063B_ADC (R52.2)
ADC_A0A1_P: MCU063B_GPIO (EC1.9), MCU063B_ADC (R51.2)
ADC_A2A3_N: MCU063B_GPIO (EC1.17), MCU063B_ADC (R54.2)
ADC_A2A3_P: MCU063B_GPIO (EC1.15), MCU063B_ADC (R53.2)
ADC_A4A5_N: MCU063B_GPIO (EC1.23), MCU063B_ADC (R56.2)
ADC_A4A5_P: MCU063B_GPIO (EC1.21), MCU063B_ADC (R55.2)
ADC_B0B1_N: MCU063B_GPIO (EC1.14), MCU063B_ADC (R61.2)
ADC_B0B1_P: MCU063B_GPIO (EC1.12), MCU063B_ADC (R60.2)
ADC_B2B3_N: MCU063B_GPIO (EC1.20), MCU063B_ADC (R63.2)
ADC_B2B3_P: MCU063B_GPIO (EC1.18), MCU063B_ADC (R62.2)
ADC_B4B5_N: MCU063B_GPIO (EC1.26), MCU063B_ADC (R65.2)
ADC_B4B5_P: MCU063B_GPIO (EC1.24), MCU063B_ADC (R64.2)
ADC_C2C3_N: MCU063B_GPIO (EC1.33), MCU063B_ADC (R68.2)
ADC_C2C3_P: MCU063B_GPIO (EC1.31), MCU063B_ADC (R67.2)
ADC_C4C5_N: MCU063B_GPIO (EC1.39), MCU063B_ADC (R70.2)
ADC_C4C5_P: MCU063B_GPIO (EC1.37), MCU063B_ADC (R69.2)
ADC_D0D1_N: MCU063B_GPIO (EC1.30), MCU063B_ADC (R73.2)
ADC_D0D1_P: MCU063B_GPIO (EC1.28), MCU063B_ADC (R72.2)
ADC_D2D3_N: MCU063B_GPIO (EC1.36), MCU063B_ADC (R75.2)
ADC_D2D3_P: MCU063B_GPIO (EC1.34), MCU063B_ADC (R74.2)
ADC_D4D5_N: MCU063B_GPIO (EC1.42), MCU063B_ADC (R81.2)
ADC_D4D5_P: MCU063B_GPIO (EC1.40), MCU063B_ADC (R76.2)
ADC_IN1415_N: MCU063B_GPIO (EC1.27), MCU063B_ADC (R59.2)
ADC_IN1415_P: MCU063B_GPIO (EC1.25), MCU063B_ADC (R58.2)
EMU_SCI-RX: MCU063B_Emulator (U2:A.38), MCU063B_Emulator_interface (U9:A.2)
EMU_SCI-TX: MCU063B_Emulator (U2:A.39), MCU063B_Emulator_interface (U8:A.6)
EMU_TCK: MCU063B_Emulator (R3:A.1 U2:A.16), MCU063B_Emulator_interface (U6:A.2)
EMU_TDI: MCU063B_Emulator (U2:A.17), MCU063B_Emulator_interface (U5:A.2)
EMU_TDO: MCU063B_Emulator (U2:A.18), MCU063B_Emulator_interface (U8:A.7)
EMU_TMS: MCU063B_Emulator (R2:A.1 U2:A.19), MCU063B_Emulator_interface (U6:A.3)
EMU_TRSTn: MCU063B_Emulator (U2:A.21), MCU063B_Emulator_interface (U5:A.3)
ENET_PHY_CLK: MCU063B_Support (R35.2), MCU063B_EtherNET (U17.23)
ERRORSTS: MCU063B_GPIO (EC2.178), MCU063B_Support (R18.2 TP1.1 U1.U19)
HSEC_ADC-VREFHI: MCU063B_GPIO (EC1.45), MCU063B_ADC (R47.1)
HSEC_GPIO8: MCU063B_GPIO (EC1.57), MCU063B_Support (R21.2)
HSEC_GPIO9: MCU063B_GPIO (EC1.59), MCU063B_Support (R23.2)
HSEC_GPIO10: MCU063B_GPIO (EC1.61), MCU063B_Support (R22.1)
HSEC_GPIO25: MCU063B_GPIO (EC1.77), MCU063B_Support (R24.1)
HSEC_GPIO26: MCU063B_GPIO (EC1.79), MCU063B_Support (R25.2)
HSEC_GPIO27: MCU063B_GPIO (EC1.81), MCU063B_Support (R27.2)
MCU_GPIO8: MCU063B_GPIO (U1.G2), MCU063B_Support (J2.1 R21.1)
MCU_GPIO9: MCU063B_GPIO (U1.G3), MCU063B_Support (J2.3 R23.1)
MCU_GPIO10: MCU063B_GPIO (U1.B2), MCU063B_Support (J2.2 R22.2)
MCU_GPIO25: MCU063B_GPIO (U1.K2), MCU063B_Support (J2.6 R24.2)
MCU_GPIO26: MCU063B_GPIO (U1.K1), MCU063B_Support (J2.5 R25.1)
MCU_GPIO27: MCU063B_GPIO (U1.L1), MCU063B_Support (J2.7 R27.1)
MCU_GPIO28: MCU063B_GPIO (EC1.76 U1.V11), MCU063B_Emulator_interface (S1:A.3)
MCU_GPIO29: MCU063B_GPIO (EC1.78 U1.W11), MCU063B_Emulator_interface (U8:A.3)
MCU_GPIO31: MCU063B_GPIO (EC1.82 U1.U11), MCU063B_Support (R11.1 U2.1)
MCU_GPIO34: MCU063B_GPIO (EC1.86 U1.U14), MCU063B_Support (R12.1 U2.3)
MCU_GPIO42: MCU063B_GPIO (U1.D19), MCU063B_USB (R95.1)
MCU_GPIO43: MCU063B_GPIO (U1.C19), MCU063B_USB (R96.1)
MCU_GPIO44: MCU063B_GPIO (U1.K18), MCU063B_EtherNET (U17.2)
MCU_GPIO46: MCU063B_GPIO (U1.E19), MCU063B_USB (R98.1 R100.2)
MCU_GPIO47: MCU063B_GPIO (U1.E18), MCU063B_USB (R101.1)
MCU_GPIO72: MCU063B_GPIO (EC2.139 R8.1), MCU063B_Support (R31.2 S2.2)
MCU_GPIO75: MCU063B_GPIO (U1.D16), MCU063B_EtherNET (U17.4)
MCU_GPIO84: MCU063B_GPIO (EC2.151 U1.A11), MCU063B_Support (R32.1 S2.1)
MCU_GPIO100: MCU063B_GPIO (U1.H1), MCU063B_Support (J1.3)
MCU_GPIO101: MCU063B_GPIO (U1.H2), MCU063B_Support (J1.7)
MCU_GPIO102: MCU063B_GPIO (U1.H3), MCU063B_Support (J1.5)
MCU_GPIO103: MCU063B_GPIO (U1.J1), MCU063B_Support (J1.2 R13.1)
MCU_GPIO105: MCU063B_GPIO (U1.J3), MCU063B_EtherNET (U17.20)
MCU_GPIO106: MCU063B_GPIO (U1.L2), MCU063B_EtherNET (R112.2 U17.19)
MCU_GPIO107: MCU063B_GPIO (EC2.170 U1.L3), MCU063B_Support (R28.2)
MCU_GPIO108: MCU063B_GPIO (U1.L4), MCU063B_EtherNET (R113.1 U17.8)
MCU_GPIO109: MCU063B_GPIO (U1.N2), MCU063B_EtherNET (U17.27)
MCU_GPIO110: MCU063B_GPIO (U1.M2), MCU063B_EtherNET (U17.29)
MCU_GPIO111: MCU063B_GPIO (U1.M4), MCU063B_EtherNET (U17.25)
MCU_GPIO112: MCU063B_GPIO (U1.M3), MCU063B_EtherNET (U17.26)
MCU_GPIO113: MCU063B_GPIO (U1.N4), MCU063B_EtherNET (U17.28)
MCU_GPIO114: MCU063B_GPIO (U1.N3), MCU063B_EtherNET (U17.30)
MCU_GPIO115: MCU063B_GPIO (U1.V12), MCU063B_EtherNET (U17.31)
MCU_GPIO116: MCU063B_GPIO (U1.W10), MCU063B_EtherNET (U17.32)
MCU_GPIO117: MCU063B_GPIO (U1.U12), MCU063B_EtherNET (U17.1)
MCU_GPIO118: MCU063B_GPIO (U1.T12), MCU063B_EtherNET (U17.3)
MCU_GPIO119: MCU063B_GPIO (U1.T15), MCU063B_EtherNET (U17.18)
MCU_GPIO120: MCU063B_GPIO (U1.U15), MCU063B_USB (R97.1)
MCU_GPIO121: MCU063B_GPIO (U1.W16), MCU063B_USB (R99.1)
MCU_GPIO122: MCU063B_GPIO (U1.T8), MCU063B_EtherNET (U17.5)
MCU_GPIO123: MCU063B_GPIO (U1.U8), MCU063B_EtherNET (U17.6)
MCU_GPIO124: MCU063B_GPIO (U1.V8), MCU063B_EtherNET (U17.7)
MCU_GPIO129: MCU063B_GPIO (U1.T10), MCU063B_EtherCAT (U21.3)
MCU_GPIO130: MCU063B_GPIO (U1.U10), MCU063B_EtherCAT (U21.2)
MCU_GPIO131: MCU063B_GPIO (U1.V10), MCU063B_EtherCAT (U21.4)
MCU_GPIO132: MCU063B_GPIO (U1.W18), MCU063B_EtherCAT (U21.5)
MCU_GPIO134: MCU063B_GPIO (U1.V18), MCU063B_EtherCAT (U21.6)
MCU_GPIO135: MCU063B_GPIO (U1.U18), MCU063B_EtherCAT (U21.7)
MCU_GPIO136: MCU063B_GPIO (U1.T17), MCU063B_EtherCAT (R155.2 U21.26)
MCU_GPIO137: MCU063B_GPIO (U1.T18), MCU063B_EtherCAT (U21.25)
MCU_GPIO138: MCU063B_GPIO (U1.T19), MCU063B_EtherCAT (R147.1 U21.28)
MCU_GPIO139: MCU063B_GPIO (U1.N19), MCU063B_EtherCAT (R156.2 U21.30)
MCU_GPIO140: MCU063B_GPIO (U1.M19), MCU063B_EtherCAT (R157.2 U21.31)
MCU_GPIO141: MCU063B_GPIO (U1.M18), MCU063B_EtherCAT (R158.2 U21.32)
MCU_GPIO142: MCU063B_GPIO (U1.L19), MCU063B_EtherCAT (R159.2 U21.1)
MCU_GPIO143: MCU063B_GPIO (U1.F18), MCU063B_EtherCAT (J5.11)
MCU_GPIO144: MCU063B_GPIO (U1.F17), MCU063B_EtherCAT (J6.11)
MCU_GPIO145: MCU063B_GPIO (U1.E17), MCU063B_EtherCAT (R143.1 U20.1)
MCU_GPIO146: MCU063B_GPIO (U1.D18), MCU063B_EtherCAT (R144.1 U20.3)
MCU_GPIO148: MCU063B_GPIO (U1.D14), MCU063B_EtherCAT (J5.2 R137.1 U19.17)
MCU_GPIO149: MCU063B_GPIO (U1.A13), MCU063B_EtherCAT (J6.2 R160.1 U21.17)
MCU_GPIO150: MCU063B_GPIO (U1.B13), MCU063B_EtherCAT (R120.1 U18.5)
MCU_GPIO151: MCU063B_GPIO (U1.C13), MCU063B_EtherCAT (R121.1 U18.6)
MCU_GPIO152: MCU063B_GPIO (U1.D13), MCU063B_EtherCAT (U19.20 U21.20)
MCU_GPIO153: MCU063B_GPIO (U1.A12), MCU063B_EtherCAT (R127.2 R152.2 U19.19 U21.19)
MCU_GPIO154: MCU063B_GPIO (U1.B12), MCU063B_Support (R29.1 R33.1)
MCU_GPIO155: MCU063B_GPIO (U1.C12), MCU063B_EtherCAT (U19.18 U21.18)
MCU_GPIO156: MCU063B_GPIO (U1.D12), MCU063B_EtherCAT (U19.3)
MCU_GPIO157: MCU063B_GPIO (U1.B10), MCU063B_EtherCAT (U19.2)
MCU_GPIO158: MCU063B_GPIO (U1.C10), MCU063B_EtherCAT (U19.4)
MCU_GPIO159: MCU063B_GPIO (U1.D10), MCU063B_EtherCAT (U19.5)
MCU_GPIO160: MCU063B_GPIO (U1.B9), MCU063B_EtherCAT (U19.6)
MCU_GPIO161: MCU063B_GPIO (U1.C9), MCU063B_EtherCAT (U19.7)
MCU_GPIO162: MCU063B_GPIO (U1.D9), MCU063B_EtherCAT (R131.2 U19.26)
MCU_GPIO163: MCU063B_GPIO (U1.A8), MCU063B_EtherCAT (U19.25)
MCU_GPIO164: MCU063B_GPIO (U1.B8), MCU063B_EtherCAT (R122.1 U19.28)
MCU_GPIO165: MCU063B_GPIO (U1.C5), MCU063B_EtherCAT (R132.2 U19.30)
MCU_GPIO166: MCU063B_GPIO (U1.D5), MCU063B_EtherCAT (R133.2 U19.31)
MCU_GPIO167: MCU063B_GPIO (U1.C4), MCU063B_EtherCAT (R134.2 U19.32)
MCU_GPIO168: MCU063B_GPIO (U1.D4), MCU063B_EtherCAT (R135.2 U19.1)
MCU_TCK: MCU063B_GPIO (EC1.5), MCU063B_Support (U1.V15), MCU063B_Emulator_interface (U7:A.14)
MCU_TDI: MCU063B_GPIO (EC1.8), MCU063B_Support (U1.W13), MCU063B_Emulator_interface (U7:A.18)
MCU_TDO: MCU063B_GPIO (EC1.6), MCU063B_Support (R15.1), MCU063B_Emulator_interface (U7:A.11)
MCU_TMS: MCU063B_GPIO (EC1.3), MCU063B_Support (U1.W14), MCU063B_Emulator_interface (U7:A.12)
MCU_TRSTn: MCU063B_GPIO (EC1.4), MCU063B_Support (R16.2 U1.V14), MCU063B_Emulator_interface (U7:A.16)
MCU_XRSn: MCU063B_GPIO (EC1.120), MCU063B_Support (7 pins)
P0_PHY_CLK: MCU063B_Support (R29.2 R30.1 TP4.1), MCU063B_EtherCAT (U19.23)
P1_PHY_CLK: MCU063B_Support (R33.2 R34.1 TP5.1), MCU063B_EtherCAT (U21.23)

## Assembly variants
001: not fitted C16 C17 C17:A C18 C19 C20 C21 C22 C23 C24 C25 C26 C27 C32 C33 C34 C35 C36 C37 C38 C39 C40 C41 C42 C43 C49 C84 C86 FID1 FID2 FID3 FID4 FID5 FID6 R12:A R14:A R17 R28 R29 R33 R41 R43 R45 R46 R47 R91
002: not fitted C16 C17 C17:A C18 C19 C20 C21 C22 C23 C24 C25 C26 C27 C32 C33 C34 C35 C36 C37 C38 C39 C40 C41 C42 C43 C49 C84 C86 FID1 FID2 FID3 FID4 FID5 FID6 R12:A R14:A R17 R28 R29 R33 R39 R41 R45 R46 R47 R91
003: not fitted C16 C17 C17:A C18 C19 C20 C21 C22 C23 C24 C25 C26 C27 C29:A C32 C33 C34 C35 C36 C37 C38 C39 C40 C41 C42 C43 C49 C84 C86 FID1 FID2 FID3 FID4 FID5 FID6 R12:A R14:A R17 R28 R29 R33 R39 R41 R45 R46 R47 R91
